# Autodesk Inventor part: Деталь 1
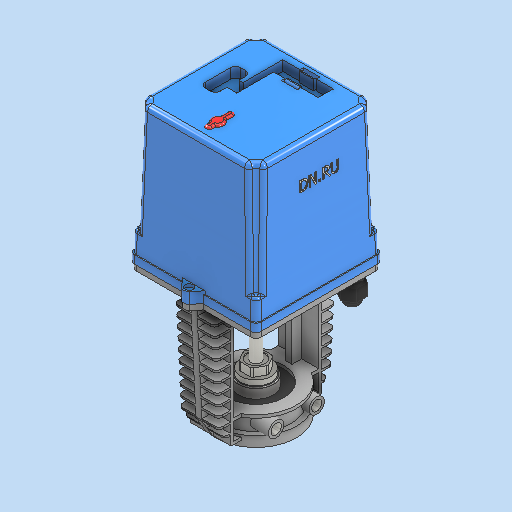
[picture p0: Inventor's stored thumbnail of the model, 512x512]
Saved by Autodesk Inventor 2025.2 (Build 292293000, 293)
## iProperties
Created: 2026-04
Part Number: Деталь 1
Material: Типовые
Document SubType Name: Modeling
Designer: igorr
Density: 1 g/cm^3
Appearance: По умолчанию
Author: igorr
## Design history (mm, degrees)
sketch "Эскиз1"
  geometry: L1 (-62.5, 62.5)-(-62.5, -62.5); L2 (-62.5, -62.5)-(62.5, -62.5); L3 (62.5, -62.5)-(62.5, 62.5); L4 (62.5, 62.5)-(-62.5, 62.5); L5 (-62.5, 62.5)-(62.5, -62.5); L6 (-62.5, -62.5)-(62.5, 62.5); L7 (0, 0)-(0, -71.5); L8 (0, -62.5)-(0, -71.5); L9 (0, 0)-(25.646, 0); L10 (0, -71.5)-(0, -61.5); C1 r 5 at (0, 66.5); 5 further points
  constraints: 20 end point, 6 midpoint, 2 parallel, 2 perpendicular, 2 point on line, 2 vertical, 1 centre point, 1 collinear, 1 symmetric about line, 4 other
  dimensions: "d0" = 125 distance of L1.start L1.end; "d1" = 125 distance of L2.end L1.end; "d2" = 71.5 distance of L7.start L7.end; "d5" = 10 distance of L7.end L10.end
extrude "Выдавливание1" new body sketch "Эскиз1" distance "d3" = 6; taper "d4" = 0 deg
chamfer "Фаска1" distance "d6" = 7.25; stored, may be unused: second distance "d7" = 2, angle "d8" = 45 deg
sketch "Эскиз2"
  geometry: L1 (-62.5, 62.5)-(-62.5, -62.5) reference; L2 (-62.5, -62.5)-(-10.25, -62.5) reference; L3 (-3.841, -69.701)-(-10.25, -62.5) reference; L4 (10.25, -62.5)-(3.841, -69.701) reference; L5 (10.25, -62.5)-(62.5, -62.5) reference; L6 (62.5, -62.5)-(62.5, 62.5) reference; L7 (62.5, 62.5)-(10.25, 62.5) reference; L8 (3.841, 69.701)-(10.25, 62.5) reference; L9 (-10.25, 62.5)-(-3.841, 69.701) reference; L10 (-10.25, 62.5)-(-62.5, 62.5) reference; L11 (61.5, 61.5)-(61.5, -61.5); L12 (61.5, -61.5)-(9.801, -61.5); L13 (9.801, -61.5)-(3.083, -69.049); L14 (-3.083, -69.049)-(-9.801, -61.5); L15 (-9.801, -61.5)-(-61.5, -61.5); L16 (-61.5, -61.5)-(-61.5, 61.5); L17 (-61.5, 61.5)-(-9.801, 61.5); L18 (-9.801, 61.5)-(-3.083, 69.049); L19 (3.083, 69.049)-(9.801, 61.5); L20 (9.801, 61.5)-(61.5, 61.5); A1 r 5 centre (0, -66.5) between (-3.841, -69.701) and (3.841, -69.701) reference; A2 r 5 centre (0, 66.5) between (3.841, 69.701) and (-3.841, 69.701) reference; A3 r 4 centre (0, -66.5) between (-3.083, -69.049) and (3.083, -69.049); A4 r 4 centre (0, 66.5) between (3.083, 69.049) and (-3.083, 69.049); 1 further point
  constraints: 20 end point, 4 point on circle, 2 centre point, 11 other
  dimensions: "d9" = 1 distance between parallel lines of L6 L11
extrude "Выдавливание2" cut sketch "Эскиз2" distance "d10" = 21; taper "d11" = 0 deg
sketch "Эскиз3"
  geometry: L1 (61.5, 61.5)-(9.801, 61.5) reference; L2 (9.801, 61.5)-(3.083, 69.049) reference; L3 (-3.083, 69.049)-(-9.801, 61.5) reference; L4 (-9.801, 61.5)-(-61.5, 61.5) reference; L5 (-61.5, 61.5)-(-61.5, -61.5) reference; L6 (-61.5, -61.5)-(-9.801, -61.5) reference; L7 (-9.801, -61.5)-(-3.083, -69.049) reference; L8 (3.083, -69.049)-(9.801, -61.5) reference; L9 (9.801, -61.5)-(61.5, -61.5) reference; L10 (61.5, -61.5)-(61.5, 61.5) reference; L11 (62.5, -62.5)-(10.25, -62.5); L12 (10.25, -62.5)-(3.841, -69.701); L13 (-3.841, -69.701)-(-10.25, -62.5); L14 (-10.25, -62.5)-(-62.5, -62.5); L15 (-62.5, -62.5)-(-62.5, 62.5); L16 (-62.5, 62.5)-(-10.25, 62.5); L17 (-10.25, 62.5)-(-3.841, 69.701); L18 (3.841, 69.701)-(10.25, 62.5); L19 (10.25, 62.5)-(62.5, 62.5); L20 (62.5, 62.5)-(62.5, -62.5); A1 r 4 centre (0, 66.5) between (3.083, 69.049) and (-3.083, 69.049) reference; A2 r 4 centre (0, -66.5) between (-3.083, -69.049) and (3.083, -69.049) reference; A3 r 5 centre (0, -66.5) between (-3.841, -69.701) and (3.841, -69.701); A4 r 5 centre (0, 66.5) between (3.841, 69.701) and (-3.841, 69.701); 1 further point
  constraints: 20 end point, 4 point on circle, 2 centre point, 11 other
  dimensions: "d12" = 1 distance between parallel lines of L9 L11
extrude "Выдавливание3" join sketch "Эскиз3" distance "d13" = 8; taper "d14" = 0 deg
sketch "Эскиз4"
  geometry: L1 (61.5, -61.5)-(61.5, 61.5); L2 (61.5, 61.5)-(-61.5, 61.5); L3 (-61.5, 61.5)-(-61.5, -61.5); L4 (-61.5, -61.5)-(61.5, -61.5); L5 (61.5, -61.5)-(-61.5, 61.5); L6 (61.5, 61.5)-(-61.5, -61.5); 1 further point
  constraints: 12 end point, 2 midpoint, 2 parallel, 1 perpendicular, 1 vertical
  dimensions: "d15" = 123 distance of L1.start L1.end; "d16" = 123 distance of L2.end L1.end
extrude "Выдавливание4" join sketch "Эскиз4" distance "d17" = 130; taper "d18" = -1 deg
sketch "Эскиз5"
  geometry: L1 (61.5, 61.5)-(61.5, -61.5) reference; L2 (61.5, -61.5)-(-61.5, -61.5) reference; L3 (-61.5, -61.5)-(-61.5, 61.5) reference; L4 (-61.5, 61.5)-(61.5, 61.5) reference; L5 (-3.841, 69.701)-(-10.25, 62.5) reference; L6 (-10.25, 62.5)-(-62.5, 62.5) reference; L7 (-62.5, 62.5)-(-62.5, -62.5) reference; L8 (-62.5, -62.5)-(-10.25, -62.5) reference; L9 (-10.25, -62.5)-(-3.841, -69.701) reference; L10 (3.841, -69.701)-(10.25, -62.5) reference; L11 (10.25, -62.5)-(62.5, -62.5) reference; L12 (62.5, -62.5)-(62.5, 62.5) reference; L13 (62.5, 62.5)-(10.25, 62.5) reference; L14 (10.25, 62.5)-(3.841, 69.701) reference; L15 (10.25, 62.5)-(14.397, 57.84); L16 (14.397, 57.84)-(-14.397, 57.84); L17 (-14.397, 57.84)-(-10.25, 62.5); L18 (62.5, 0)-(81.182, 0); L19 (10.25, -62.5)-(3.841, -69.701); L20 (-3.841, -69.701)-(-10.25, -62.5); L21 (14.397, -57.84)-(-14.397, -57.84); L22 (10.25, -62.5)-(14.397, -57.84); L23 (-14.397, -57.84)-(-10.25, -62.5); C1 r 4 at (0, 66.101); C2 r 4 at (0, -66.101); A1 r 5 centre (0, -66.5) between (-3.841, -69.701) and (3.841, -69.701) reference; A2 r 5 centre (0, 66.5) between (3.841, 69.701) and (-3.841, 69.701) reference; A3 r 5 centre (0, -66.5) between (-3.841, -69.701) and (3.841, -69.701); 1 further point
  constraints: 18 end point, 4 symmetric about line, 3 centre point, 2 horizontal, 2 point on circle, 2 point on line, 1 collinear, 1 midpoint, 2 other
  dimensions: "d19" = 8 diameter of C1
extrude "Выдавливание5" join sketch "Эскиз5" distance "d20" = 3; taper "d21" = 0 deg
sketch "Эскиз6"
  geometry: L1 (-59.231, 59.231)-(59.231, 59.231) reference; C1 r 7.5 at (59.231, 59.231); C2 r 7.5 at (-59.231, 59.231); C3 r 7.5 at (-59.231, -59.231); C4 r 7.5 at (59.231, -59.231); 1 further point
  constraints: 4 centre point, 9 other
  dimensions: "d22" = 15 diameter of C1; "d25" = 360 deg dimension on point (0, 0) L1.end (derived)
extrude "Выдавливание6" cut sketch "Эскиз6" distance "d27" = 110; taper "d28" = -2 deg
sketch "Эскиз7"
  geometry: L1 (-21.282, 47.681)-(28.718, 47.681); L2 (28.718, 47.681)-(28.718, 32.681); L3 (28.718, 32.681)-(-21.282, 32.681); L4 (-21.282, 32.681)-(-21.282, 47.681); L5 (-21.282, 47.681)-(28.718, 32.681); L6 (28.718, 47.681)-(-21.282, 32.681); L7 (-40.282, 15)-(-40.282, -10); L8 (-35.282, -15)-(-30.282, -15); L9 (-25.282, -10)-(-25.282, 15); L10 (-30.282, 20)-(-35.282, 20); L11 (-40.282, 20)-(-25.282, -15); L12 (-40.282, -15)-(-25.282, 20); L13 (-35.282, 8.5)-(-15.282, 8.5); L14 (-15.282, 8.5)-(-15.282, -3.5); L15 (-15.282, -3.5)-(-35.282, -3.5); L16 (-35.282, -3.5)-(-35.282, 8.5); L17 (-35.282, 8.5)-(-15.282, -3.5); L18 (-15.282, 8.5)-(-35.282, -3.5); L19 (-15.282, -3.5)-(-21.282, -3.5); L20 (-21.282, -3.5)-(-21.282, 50.128); L21 (-21.282, 50.128)-(-15.282, 50.128); L22 (-15.282, 50.128)-(-15.282, -3.5); L23 (-4.282, 51.181)-(-4.282, 29.181); L24 (-4.282, 29.181)-(11.718, 29.181); L25 (11.718, 29.181)-(11.718, 51.181); L26 (11.718, 51.181)-(-4.282, 51.181); L27 (-4.282, 51.181)-(11.718, 29.181); L28 (-4.282, 29.181)-(11.718, 51.181); A1 r 5 centre (-30.282, 15) between (-25.282, 15) and (-30.282, 20); A2 r 5 centre (-30.282, -10) between (-30.282, -15) and (-25.282, -10); A3 r 5 centre (-35.282, -10) between (-40.282, -10) and (-35.282, -15); A4 r 5 centre (-35.282, 15) between (-35.282, 20) and (-40.282, 15); 14 further points
  constraints: 56 end point, 10 parallel, 9 midpoint, 9 point on line, 8 point on circle, 8 tangent, 5 perpendicular, 4 centre point, 3 equal radius, 2 horizontal, 2 vertical, 1 collinear
  dimensions: "d29" = 50 distance of L1.start L1.end; "d30" = 15 distance of L1.end L2.end; "d31" = 35 distance of L11.start L12.start; "d32" = 15 distance of L11.end L12.start; "d33" = 20 distance of L13.start L13.end; "d34" = 12 distance of L13.end L14.end; "d35" = 6 distance of L14.end L19.end; "d36" = 22 distance of L23.start L23.end; "d37" = 16 distance of L24.end L23.end; "d38" = 5 radius of A1
extrude "Выдавливание7" cut sketch "Эскиз7" distance "d39" = 10; taper "d40" = 0 deg
sketch "Эскиз8"
  geometry: L1 (0, -46.285)-(0, -25.359); L2 (-15.282, 32.681)-(-15.282, -3.5) reference; L3 (3, -46.285)-(3, -25.359); L4 (-3, -25.359)-(-3, -46.285); C1 r 6 at (0, -38.032); A1 r 3 centre (0, -46.285) between (-3, -46.285) and (3, -46.285); A2 r 3 centre (0, -25.359) between (3, -25.359) and (-3, -25.359); 6 further points
  constraints: 8 end point, 4 point on circle, 4 tangent, 3 centre point, 2 parallel, 1 midpoint
  dimensions: "d41" = 12 diameter of C1; "d42" = 6 diameter of A2
extrude "Выдавливание8" join sketch "Эскиз8" distance "d43" = 2; taper "d44" = 0 deg
sketch "Эскиз9"
  geometry: L1 (-4.282, 51.181)-(11.718, 51.181) reference; L2 (11.718, 29.181)-(-4.282, 29.181) reference; L3 (11.718, 51.181)-(-4.282, 29.181); L4 (-3.282, 49.181)-(-3.282, 31.181); L5 (-3.282, 31.181)-(10.718, 31.181); L6 (10.718, 31.181)-(10.718, 49.181); L7 (10.718, 49.181)-(-3.282, 49.181); L8 (-3.282, 49.181)-(10.718, 31.181); L9 (-3.282, 31.181)-(10.718, 49.181); L10 (-3.282, 46.181)-(10.718, 46.181); L11 (10.718, 46.181)-(10.718, 34.181); L12 (10.718, 34.181)-(-3.282, 34.181); L13 (-3.282, 34.181)-(-3.282, 46.181); L14 (-3.282, 46.181)-(10.718, 34.181); L15 (10.718, 46.181)-(-3.282, 34.181); 6 further points
  constraints: 26 end point, 5 midpoint, 4 parallel, 2 perpendicular, 1 vertical
  dimensions: "d45" = 18 distance of L4.start L4.end; "d46" = 14 distance of L5.end L4.end; "d47" = 12 distance of L10.end L11.end
extrude "Выдавливание9" join sketch "Эскиз9" stored distance "d48" = 2; taper "d49" = 0 deg
sketch "Эскиз11"
  geometry: C1 r 22.5 at (0, 0); C2 r 25 at (0, 0); 1 further point
  constraints: 2 centre point, 1 coincident
  dimensions: "d50" = 45 diameter of C1; "d51" = 2.5 radial gap between concentric circles of C1 C2
extrude "Выдавливание10" cut sketch "Эскиз11" distance "d52" = 10; taper "d53" = 0 deg
sketch "Эскиз12"
  geometry: L1 (3, -61.5)-(3, 61.5); L2 (3, 61.5)-(-3, 61.5); L3 (-3, 61.5)-(-3, -61.5); L4 (-3, -61.5)-(3, -61.5); L5 (3, -61.5)-(-3, 61.5); L6 (3, 61.5)-(-3, -61.5); L7 (-9.801, 61.5)-(-61.5, 61.5) reference; L8 (3, -32.5)-(-3, -32.5); L9 (-3, -32.5)-(-3, 32.5); L10 (-3, 32.5)-(3, 32.5); L11 (3, 32.5)-(3, -32.5); L12 (3, -32.5)-(-3, 32.5); L13 (-3, -32.5)-(3, 32.5); L14 (20, -45.032)-(-20, -45.032); L15 (-20, -45.032)-(-20, -42.032); L16 (-20, -42.032)-(20, -42.032); L17 (20, -42.032)-(20, -45.032); L18 (20, -45.032)-(-20, -42.032); L19 (-20, -45.032)-(20, -42.032); L20 (-3, 0)-(-7.639, 0); L21 (20, 42.032)-(20, 45.032); L22 (-20, 42.032)-(20, 42.032); L23 (-20, 45.032)-(20, 42.032); L24 (20, 45.032)-(-20, 42.032); L25 (20, 45.032)-(-20, 45.032); L26 (-20, 45.032)-(-20, 42.032); 15 further points
  constraints: 50 end point, 9 midpoint, 7 parallel, 5 symmetric about line, 3 perpendicular, 2 collinear, 1 horizontal
  dimensions: "d54" = 6 distance of L2.end L1.end; "d55" = 65 distance of L8.end L9.end; "d58" = 40 distance of L14.start L14.end; "d59" = 3 distance of L14.end L15.end
extrude "Выдавливание11" join sketch "Эскиз12" distance "d56" = 120; taper "d57" = 0 deg
sketch "Эскиз13"
  geometry: C1 r 25 at (0, 0) reference; C2 r 40 at (0, 0); 1 further point
  constraints: 1 centre point, 1 coincident
  dimensions: "d60" = 80 diameter of C2
extrude "Выдавливание12" join sketch "Эскиз13" stored distance "d61" = 10; taper "d63" = 0 deg; dims "d62" = 2, "d64" = 0
sketch "Эскиз14"
  geometry: C1 r 40 at (0, 0) reference; C2 r 35 at (0, 0); 1 further point
  constraints: 1 centre point, 1 coincident
  dimensions: "d65" = 70 diameter of C2
extrude "Выдавливание13" join sketch "Эскиз14" distance "d66" = 15; taper "d67" = 0 deg
sketch "Эскиз15" dims "d12" = 1
  geometry: L1 (-20, 42.032)-(-20, -42.032); L2 (-20, -42.032)-(20, -42.032); L3 (20, -42.032)-(20, 42.032); L4 (20, 42.032)-(-20, 42.032); L5 (-20, 42.032)-(20, -42.032); L6 (-20, -42.032)-(20, 42.032); L7 (3, -42.032)-(20, -42.032) reference; C1 r 40 at (0, 0); C2 r 27.5 at (0, 0); A1 r 40 centre (0, 0) between (3, -39.887) and (3, 39.887) reference; 5 further points
  constraints: 12 end point, 2 centre point, 2 coincident, 2 midpoint, 2 parallel, 1 collinear, 1 concentric, 1 perpendicular, 1 vertical
  dimensions: "d68" = 40 distance of L2.end L1.end; "d69" = 55 diameter of C2
extrude "Выдавливание14" join sketch "Эскиз15" distance "d70" = 3; taper "d71" = 0 deg
sketch "Эскиз16"
  geometry: L1 (20, 42.032)-(20, -42.032); L2 (20, -42.032)-(-20, -42.032); L3 (-20, -42.032)-(-20, 42.032); L4 (-20, 42.032)-(20, 42.032); L5 (20, 42.032)-(-20, -42.032); L6 (20, -42.032)-(-20, 42.032); A1 r 40 centre (0, 0) between (-20, 34.641) and (-20, -34.641) reference; 1 further point
  constraints: 12 end point, 2 midpoint, 2 parallel, 1 perpendicular, 1 vertical
extrude "Выдавливание15" join sketch "Эскиз16" distance "d72" = 3; taper "d73" = 0 deg
sketch "Эскиз17"
  geometry: L1 (0, -61.5)-(-120, -61.5) reference; L2 (0, -61.5)-(-9, -61.5); L3 (0, -42.032)-(-97, -42.032) reference; L4 (-9, -61.5)-(-9, -42.032); L5 (-9, -42.032)-(-11, -42.032); L6 (-11, -42.032)-(-11, -61.5); L7 (-11, -61.5)-(-9, -61.5); 3 further points
  constraints: 10 end point, 2 parallel, 2 point on line, 1 perpendicular, 1 vertical
  dimensions: "d74" = 9 distance of L1.start L2.end; "d75" = 2 distance of L5.end L4.end
extrude "Выдавливание16" join sketch "Эскиз17" stored distance "d76" = 40; taper "d77" = 0 deg
pattern_linear "Прямоуг.массив1"
mirror "Зеркальное отражение1"
sketch "Эскиз18"
  geometry: L1 (10.391, 0)-(0, 0) reference; L2 (0, 0)-(-11.293, 18.805); L3 (-16.468, 120)-(-16.468, 111) reference; L4 (-11.293, 18.805)-(-16.468, 120); L5 (0, 0)-(-16.468, 0) reference; L6 (-16.468, 120)-(-16.468, 0); L7 (-16.468, 0)-(0, 0); L8 (45.032, 120)-(45.032, 160.583); L9 (79.673, 0)-(90.064, 0); L10 (90.064, 0)-(101.357, 18.805); L11 (106.532, 120)-(106.532, 111); L12 (101.357, 18.805)-(106.532, 120); L13 (90.064, 0)-(106.532, 0); L14 (106.532, 120)-(106.532, 0); L15 (106.532, 0)-(90.064, 0); 2 further points
  constraints: 24 end point, 6 symmetric about line, 2 perpendicular, 1 vertical
extrude "Выдавливание17" cut sketch "Эскиз18" distance "d81" = 40; taper "d82" = 0 deg
sketch "Эскиз19"
  geometry: C1 r 27.5 at (0, 0) reference; C2 r 15 at (0, 0); 1 further point
  constraints: 1 centre point, 1 coincident
  dimensions: "d83" = 30 diameter of C2
extrude "Выдавливание18" join sketch "Эскиз19" distance "d84" = 15; taper "d85" = 0 deg
sketch "Эскиз20"
  geometry: L1 (12.372, 0)-(6.186, -10.715); L2 (6.186, -10.715)-(-6.186, -10.715); L3 (-6.186, -10.715)-(-12.372, 0); L4 (-12.372, 0)-(-6.186, 10.715); L5 (-6.186, 10.715)-(6.186, 10.715); L6 (6.186, 10.715)-(12.372, 0); 2 further points
  constraints: 12 end point, 1 coincident, 13 other
extrude "Выдавливание19" join sketch "Эскиз20" distance "d86" = 8; taper "d87" = 0 deg
sketch "Эскиз21"
  geometry: C1 r 9 at (0, 0); 1 further point
  constraints: 1 centre point, 1 coincident
  dimensions: "d88" = 18 diameter of C1
extrude "Выдавливание20" cut sketch "Эскиз21" distance "d89" = 1; taper "d90" = 0 deg
sketch "Эскиз22"
  geometry: C1 r 5 at (0, 0); 1 further point
  constraints: 1 centre point, 1 coincident
  dimensions: "d91" = 10 diameter of C1
extrude "Выдавливание21" join sketch "Эскиз22" distance "d92" = 48; taper "d93" = 0 deg
sketch "Эскиз23"
  geometry: C1 r 6.5 at (0, 0); 1 further point
  constraints: 1 centre point, 1 coincident
  dimensions: "d94" = 13 diameter of C1
extrude "Выдавливание22" join sketch "Эскиз23" distance "d95" = 15; taper "d96" = 0 deg
sketch "Эскиз24"
  geometry: L1 (-11.771, -15)-(-28.52, -15); L2 (-28.52, -15)-(-28.52, 15); L3 (-28.52, 15)-(-11.771, 15); L4 (-11.771, 15)-(-11.771, -15); L5 (-15, -6.5)-(-15, 6.5) reference; L6 (-11.771, -15)-(-28.52, 15); L7 (-28.52, -15)-(-11.771, 15); 2 further points
  constraints: 12 end point, 3 parallel, 2 midpoint, 1 perpendicular
  dimensions: "d97" = 30 distance of L1.end L2.end
extrude "Выдавливание23" join sketch "Эскиз24" stored distance "d98" = 8; taper "d99" = 0 deg
sketch "Эскиз25"
  geometry: L1 (-0.5, 21)-(8.5, 21); L2 (8.5, 21)-(8.5, 9); L3 (8.5, 9)-(-0.5, 9); L4 (-0.5, 9)-(-0.5, 21); L5 (-0.5, 21)-(8.5, 9); L6 (8.5, 21)-(-0.5, 9); A1 r 6.5 centre (4, 15) between (0, 20.123) and (0, 9.877) reference; 1 further point
  constraints: 12 end point, 2 midpoint, 2 parallel, 1 horizontal, 1 perpendicular
  dimensions: "d100" = 9 distance of L1.start L1.end; "d101" = 12 distance of L1.end L2.end
extrude "Выдавливание24" join sketch "Эскиз25" distance "d102" = 15; taper "d103" = 0 deg
sketch "Эскиз26"
  geometry: L1 (-1, -2.664)-(13, -2.664); L2 (13, -2.664)-(13, 4.336); L3 (6, 11.336)-(6, 11.336); L4 (-1, 4.336)-(-1, -2.664); L5 (-1, -2.664)-(13, 11.336); L6 (13, -2.664)-(-1, 11.336); A1 r 7 centre (6, 4.336) between (6, 11.336) and (-1, 4.336); A2 r 7 centre (6, 4.336) between (13, 4.336) and (6, 11.336); 3 further points
  constraints: 12 end point, 4 point on circle, 4 point on line, 4 tangent, 2 centre point, 2 midpoint, 2 parallel, 1 concentric, 1 horizontal, 1 perpendicular
  dimensions: "d104" = 14 distance of L1.start L1.end; "d105" = 14 distance of L5.end L1.end; "d106" = 7 radius of A1
extrude "Выдавливание25" join sketch "Эскиз26" distance "d107" = 2; taper "d108" = 0 deg
sketch "Эскиз27"
  geometry: L1 (-7, -14.435)-(7, -14.435) reference; L2 (-7, -14.435)-(7, -14.435); L3 (7, -14.435)-(7, -11.771); L4 (7, -11.771)-(-7, -11.771); L5 (-7, -11.771)-(-7, -14.435); 1 further point
  constraints: 8 end point, 3 equal length, 1 perpendicular
extrude "Выдавливание26" join sketch "Эскиз27" stored distance "d109" = 2; taper "d110" = 0 deg
mirror "Зеркальное отражение2"
sketch "Эскиз31"
  geometry: L1 (-100, -34.871)-(-115, -34.871) reference; L2 (-107.5, -34.871)-(-107.5, 34.871); L3 (-100, 34.871)-(-115, 34.871) reference; C1 r 7.5 at (-107.5, 0); C2 r 5 at (-107.5, 0); 1 further point
  constraints: 3 midpoint, 2 centre point, 2 end point, 1 coincident
  dimensions: "d117" = 10 diameter of C2
extrude "Выдавливание30" join sketch "Эскиз31" distance "d118" = 40; taper "d119" = 0 deg
sketch "Эскиз32"
  geometry: L1 (-100, 34.871)-(-115, 34.871) reference; L2 (-107.5, 34.871)-(-107.5, -34.871); L3 (-115, -34.871)-(-100, -34.871) reference; L4 (-100, 0)-(-100, 34.871) reference; L5 (-97, 27.5)-(-97, -27.5) reference; L6 (-97, 0)-(-91.595, 0); C1 r 7.5 at (-107.5, 20.02); C2 r 5 at (-107.5, 20.02); C3 r 7.5 at (-107.5, -20.02); C4 r 5 at (-107.5, -20.02); 1 further point
  constraints: 4 centre point, 4 end point, 4 midpoint, 2 coincident, 2 symmetric about line, 1 horizontal, 1 point on line, 1 tangent, 2 other
  dimensions: "d120" = 10 diameter of C2
extrude "Выдавливание31" join sketch "Эскиз32" distance "d121" = 40; taper "d122" = 0 deg
sketch "Эскиз33"
  geometry: L1 (58.359, -47.515)-(52.809, -56.952); L2 (52.809, -56.952)-(41.862, -56.863); L3 (41.862, -56.863)-(36.465, -47.338); L4 (36.465, -47.338)-(42.015, -37.902); L5 (42.015, -37.902)-(52.963, -37.991); L6 (52.963, -37.991)-(58.359, -47.515); L7 (45.512, 27.742)-(45.512, 7.03); L8 (45.512, 7.03)-(57.512, 7.03); L9 (57.512, 7.03)-(57.512, 27.742); L10 (57.512, 27.742)-(45.512, 27.742); L11 (45.512, 27.742)-(57.512, 7.03); L12 (45.512, 7.03)-(57.512, 27.742); C1 r 10 at (47.412, 43.457); 3 further points
  constraints: 24 end point, 2 midpoint, 2 parallel, 1 centre point, 1 perpendicular, 1 vertical, 13 other
  dimensions: "d123" = 20 diameter of C1; "d124" = 12 distance of L8.end L7.end
extrude "Выдавливание32" join sketch "Эскиз33" distance "d125" = 3; taper "d126" = 0 deg
node "Непосредственное редактирование1"
sketch "Эскиз34"
  geometry: L1 (10.948, 0)-(0, 0) reference; L2 (10.948, -18.962)-(0, -18.962) reference; L3 (10.948, 0)-(0, -18.962); C1 r 7.5 at (5.474, -9.481); 1 further point
  constraints: 2 end point, 1 centre point, 1 midpoint
  dimensions: "d130" = 15 diameter of C1
extrude "Выдавливание33" join sketch "Эскиз34" distance "d131" = 5; taper "d132" = 0 deg
sketch "Эскиз35"
  geometry: L1 (9.679, -5.536)-(0.046, -11.15); L2 (0.046, -11.15)-(-9.634, -5.615); L3 (-9.634, -5.615)-(-9.679, 5.536); L4 (-9.679, 5.536)-(-0.046, 11.15); L5 (-0.046, 11.15)-(9.634, 5.615); L6 (9.634, 5.615)-(9.679, -5.536); C1 r 7.5 at (0, 0) reference; 2 further points
  constraints: 12 end point, 1 coincident, 13 other
extrude "Выдавливание34" join sketch "Эскиз35" distance "d133" = 12; taper "d134" = 0 deg
sketch "Эскиз36"
  geometry: C1 r 9 at (0, 0); C2 r 7.5 at (0, 0) reference; C3 r 4 at (0, 0); 1 further point
  constraints: 2 centre point, 1 coincident
  dimensions: "d135" = 18 diameter of C1; "d136" = 8 diameter of C3
extrude "Выдавливание35" join sketch "Эскиз36" distance "d137" = 8; taper "d138" = 0 deg
sketch "Эскиз37"
  geometry: L1 (43.658, 99.007)-(55.919, 99.007); L2 (55.919, 99.007)-(55.919, 95.895); L3 (55.919, 95.895)-(43.658, 95.895); L4 (43.658, 95.895)-(43.658, 99.007); 1 further point
  constraints: 2 other
feature "Рельеф1" sketch "Эскиз37" dims "d139" = 0.5, "d140" = 0
fillet "Сопряжение1" dims "d145" = 5
fillet "Сопряжение2" dims "d146" = 2
fillet "Сопряжение3" dims "d147" = 4
fillet "Сопряжение4" dims "d148" = 2
sketch "Эскиз40"
  geometry: C1 r 2.5 at (-7.435, 0); A1 r 7 centre (-7.435, 0) between (-7.435, -7) and (-7.435, 7) reference; 1 further point
  constraints: 1 centre point, 1 coincident
  dimensions: "d149" = 5 diameter of C1
extrude "Выдавливание38" join sketch "Эскиз40" stored distance "d150" = 25; taper "d151" = 0 deg
sketch "Эскиз41"
  geometry: L1 (5, -30)-(-5, -30) reference; L2 (0, -30)-(0, -34.078); C1 r 3 at (-10.145, -22.095); C2 r 3 at (10.145, -22.095); 1 further point
  constraints: 2 centre point, 2 end point, 1 midpoint, 1 symmetric about line, 1 vertical, 1 other
  dimensions: "d152" = 6 diameter of C1
extrude "Выдавливание39" cut sketch "Эскиз41" stored distance "d153" = 25; taper "d154" = 0 deg
sketch "Эскиз42"
  geometry: C1 r 27.5 at (0, 0) reference; 1 further point
extrude "Выдавливание40" cut sketch "Эскиз42" distance "d155" = 3; taper "d156" = 0 deg
sketch "Эскиз43"
  geometry: C1 r 15 at (0, 0) reference; C2 r 17 at (0, 0); 1 further point
  constraints: 1 centre point
  dimensions: "d157" = 2 radial gap between concentric circles of C1 C2
extrude "Выдавливание41" join sketch "Эскиз43" distance "d158" = 10; taper "d159" = 0 deg
fillet "Сопряжение5" dims "d160" = 1
node "Твердое тело1"
node "Спроецированная петля1"
node "Спроецированная петля2"
node "Спроецированная петля3"
node "Эскиз — круговой массив1" dims "d25" = 360 deg (derived)
feature "Перенос1" dims "d129" = 2
other parameters: "d127" = 0, "d128" = 0
